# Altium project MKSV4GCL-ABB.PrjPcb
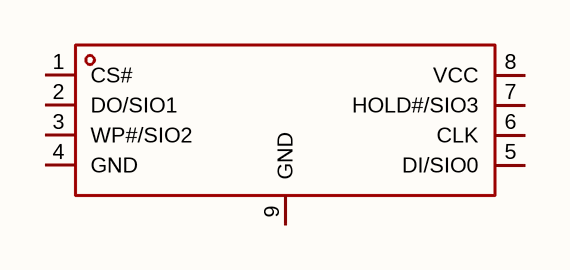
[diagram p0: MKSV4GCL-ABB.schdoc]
1 sheet, 1 parts. Net scope: global (net labels, ports and power ports of the same name join across sheets).

## Sheet MKSV4GCL-ABB.schdoc
size 127 x 101 mm

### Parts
U?  mksv4gcl-abb  [WSON-8_L8.0-W6.0-P1.27-TL_MKSV4GCL-ABB]  (value not drawn)

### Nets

Not connected (* = marked no-connect by the designer): U? 1(CS#) 2(DO/SIO1) 3(WP#/SIO2) 4(GND) 5(DI/SIO0) 6(CLK) 7(HOLD#/SIO3) 8(VCC) 9(GND)

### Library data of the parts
U? = mksv4gcl-abb: 存储容量:4Gbit;时钟频率(fc):90MHz;工作电压:2.7V~3.6V;; Manufacturer: MK(米客方德); AddInBom: yes; ModelId: 2def4ccca8cd4b63a419e9bde5a0cfa3; ModelTransform: 314.96,236.22,0,0,0,0,-0.005,0,0; Memory Size: 4Gbit; Interface: SPI; Clock Frequency: 90MHz; Page Program time (TPP): 400us; Block Erase Time(tBE): 3ms; Data Retention - TDR (Year): 10年; Standby Supply Current: 100uA; Program / Erase Cycles: 6万次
